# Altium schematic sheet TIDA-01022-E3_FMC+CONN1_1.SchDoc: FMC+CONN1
size 431 x 279 mm; Date: Not shown in title block; ApprovedBy: Not shown in title block; CheckedBy: Not shown in title block; Author: Not shown in title block; CompanyName: Not shown in title block; DrawnBy: Avinash N; Engineer: Not shown in title block; Organization: Not shown in title block; Address1: Not shown in title block; Address2: Not shown in title block; Address3: Not shown in title block; Address4: Not shown in title block; DocumentNumber: 1; Revision: Use project parameter SCH_Rev; SheetNumber: 17; SheetTotal: 26; PageSetup: Record=PageOptions¦CenterHorizontal=True¦CenterVertical=True¦PrintScale=1.00¦XCorrection=1.00¦YCorrection=1.00¦PrintKind=0¦BorderSize=5000000¦LeftOffset=0¦BottomOffset=0¦Orientation=2¦PaperLength=1000¦PaperWidth=1000¦Scale=100¦PaperSource=15¦PrintQuality=600¦MediaType=1¦DitherType=10¦PaperKind=Letter¦PrintScaleMode=1
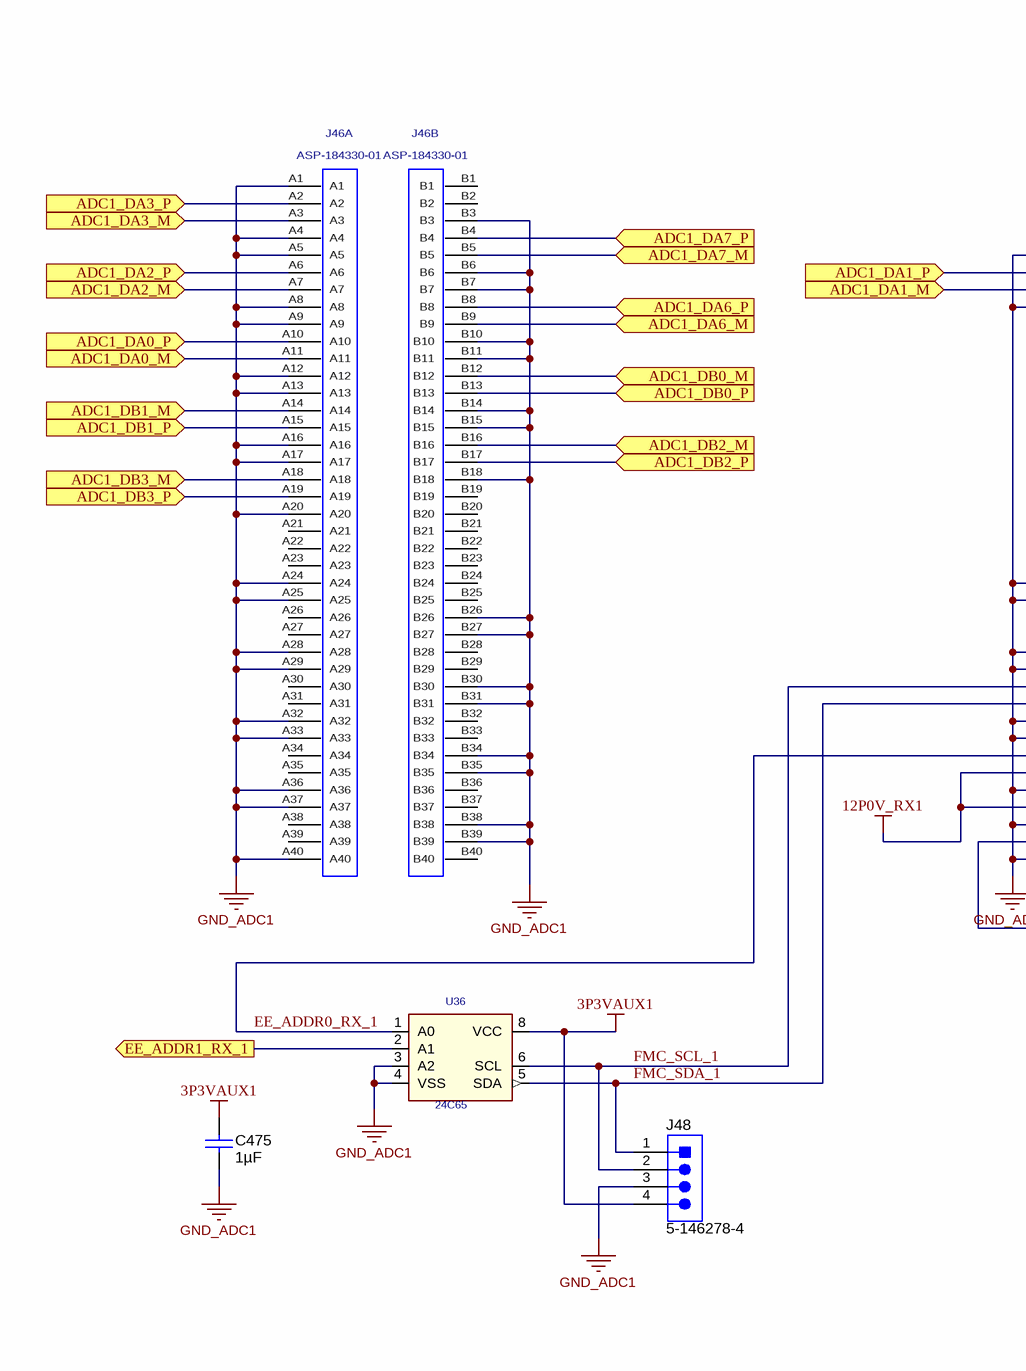
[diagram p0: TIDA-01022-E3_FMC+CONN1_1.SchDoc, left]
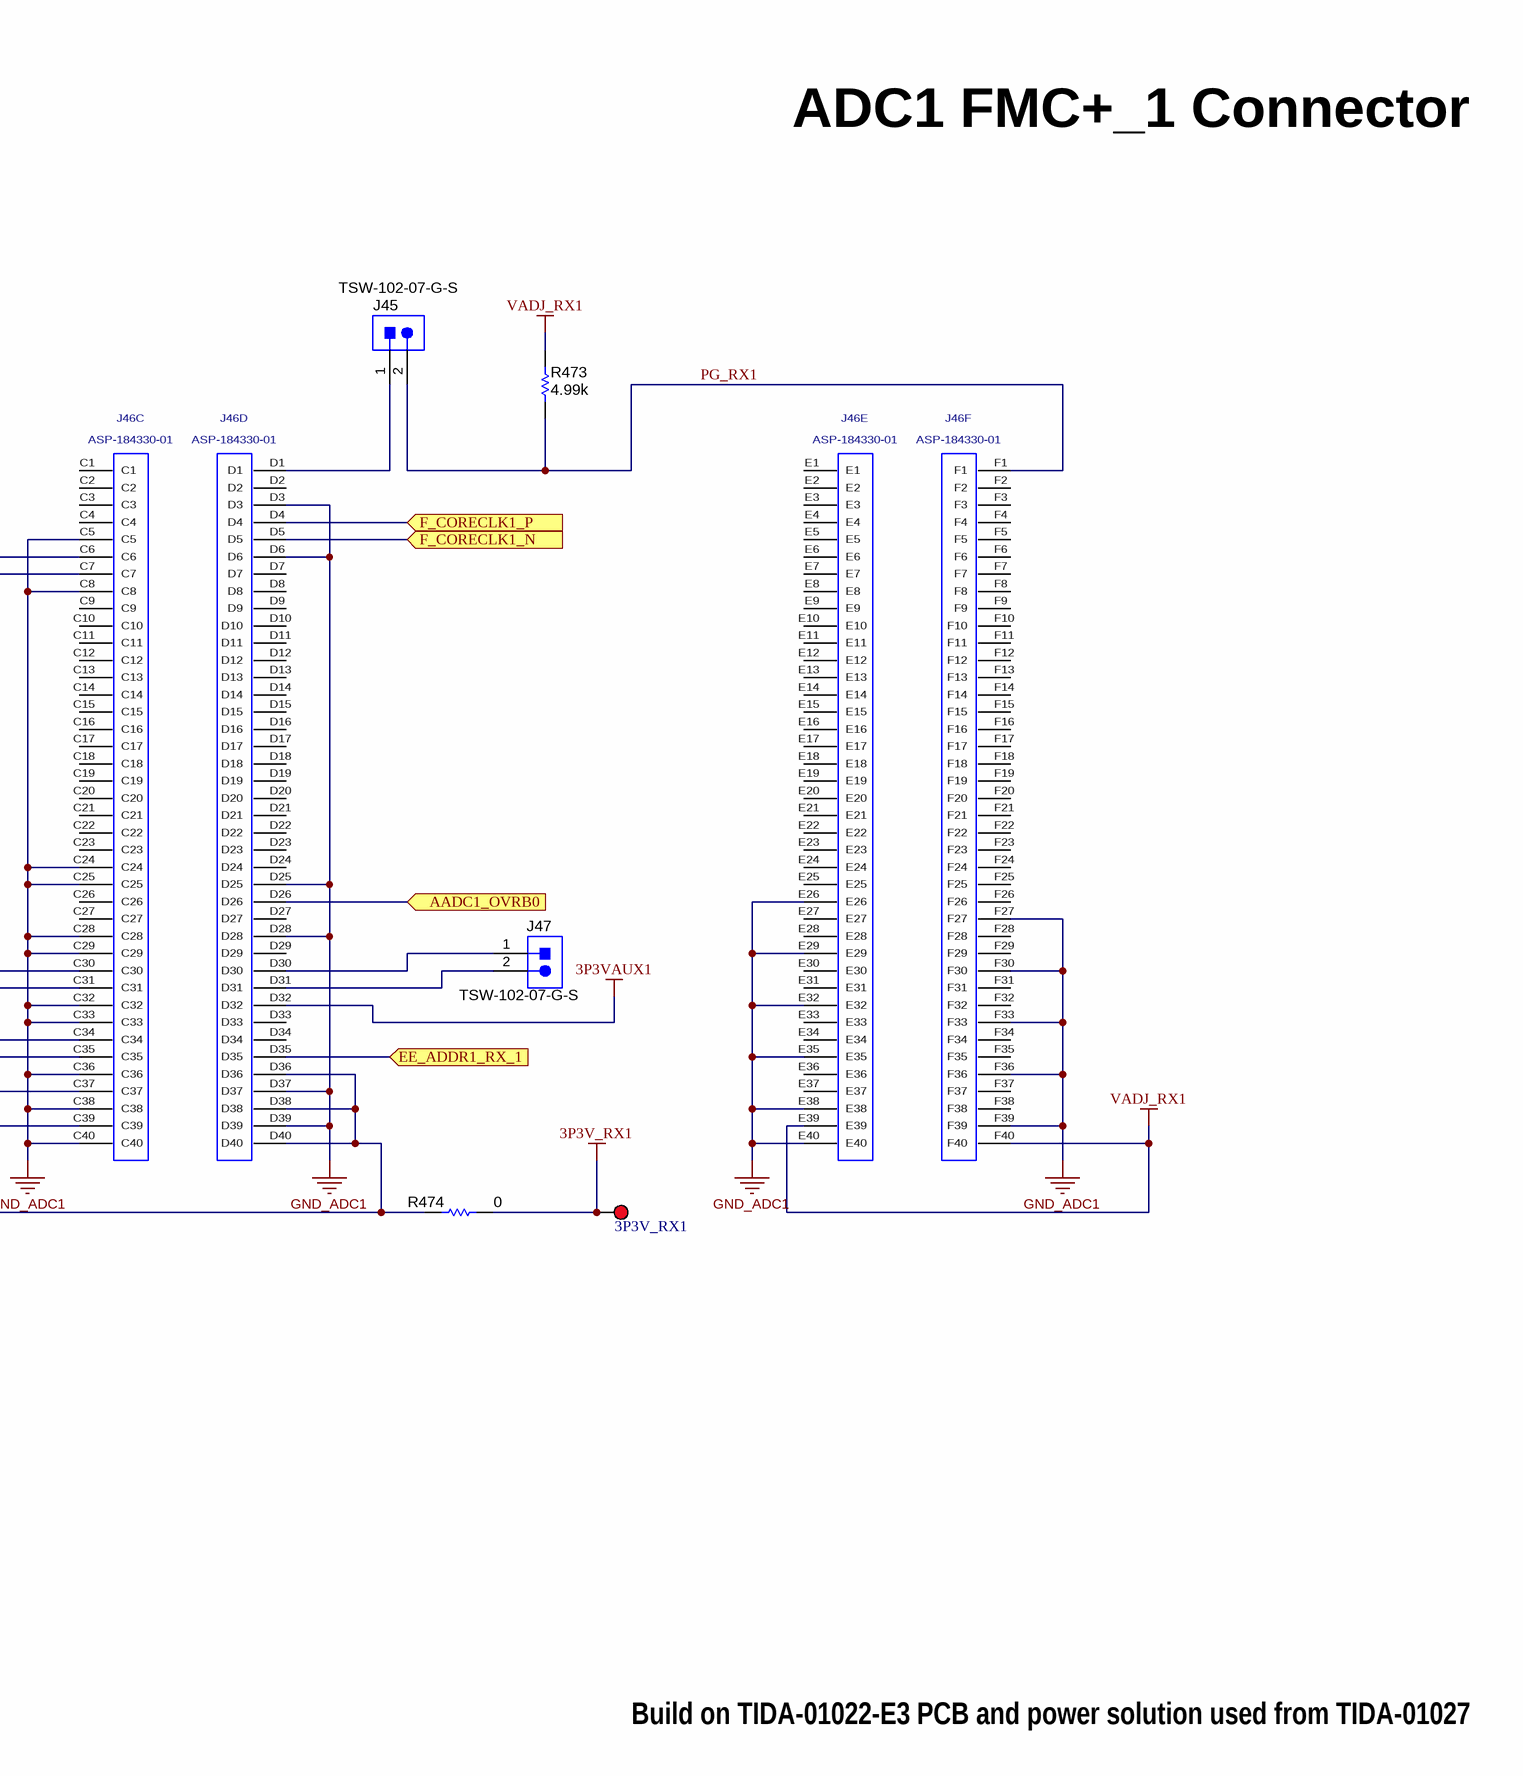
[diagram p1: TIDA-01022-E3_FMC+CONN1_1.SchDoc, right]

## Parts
3P3V_RX1  5000  [Keystone5000]  (value not drawn)
C475  ValueDisplayed: 1µF  [0603]  (hidden comment: C1608X5R1A105K080AC)
J45  TSW-102-07-G-S  [TSW-102-07-G-S]
J46  ASP-184330-01  [ASP-184330-01]  (parts A,B,C,D,E,F of 14)
J47  TSW-102-07-G-S  [TSW-102-07-G-S]
J48  5-146278-4  [TE_5-146278-4]
R473  ValueDisplayed: 4.99k  [0402]  (hidden comment: CRCW04024K99FKED)
R474  ValueDisplayed: 0  [0402]  (hidden comment: CRCW04020000Z0ED)
U36  24C65  [SOIC127P800X216-8N]

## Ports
AADC1_OVRB0 (in), ADC1_DA0_M (in), ADC1_DA0_P (in), ADC1_DA1_M (in), ADC1_DA1_P (in), ADC1_DA2_M (in), ADC1_DA2_P (in), ADC1_DA3_M (in), ADC1_DA3_P (in), ADC1_DA6_M (in), ADC1_DA6_P (in), ADC1_DA7_M (in), ADC1_DA7_P (in), ADC1_DB0_M (in), ADC1_DB0_P (in), ADC1_DB1_M (in), ADC1_DB1_P (in), ADC1_DB2_M (in), ADC1_DB2_P (in), ADC1_DB3_M (in), ADC1_DB3_P (in), EE_ADDR1_RX_1 (in), EE_ADDR1_RX_1 (out), F_CORECLK1_N (in), F_CORECLK1_P (in)

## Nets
3P3V_RX1: 3P3V_RX1.1 R474.1
3P3VAUX1: C475.1 J46.D32 J48.4 U36.8(VCC)
12P0V_RX1: J46.C35 J46.C37
GND_ADC1: C475.2 J46.A1 J46.A4 J46.A5 J46.A8 J46.A9 J46.A12 J46.A13 J46.A16 J46.A17 J46.A20 J46.A24 J46.A25 J46.A28 J46.A29 J46.A32 J46.A33 J46.A36 J46.A37 J46.A40 J46.B3 J46.B6 J46.B7 J46.B10 J46.B11 J46.B14 J46.B15 J46.B18 J46.B26 J46.B27 J46.B30 J46.B31 J46.B34 J46.B35 J46.B38 J46.B39 J46.C5 J46.C8 J46.C24 J46.C25 J46.C28 J46.C29 J46.C32 J46.C33 J46.C36 J46.C38 J46.C40 J46.D3 J46.D6 J46.D25 J46.D28 J46.D37 J46.D39 J46.E26 J46.E29 J46.E32 J46.E35 J46.E38 J46.E40 J46.F27 J46.F30 J46.F33 J46.F36 J46.F39 J48.3 U36.3(A2) U36.4(VSS)
VADJ_RX1: J46.E39 J46.F40 R473.2
AADC1_OVRB0: J46.D26 ; port AADC1_OVRB0
ADC1_DA0_M: J46.A11 ; port ADC1_DA0_M
ADC1_DA0_P: J46.A10 ; port ADC1_DA0_P
ADC1_DA1_M: J46.C7 ; port ADC1_DA1_M
ADC1_DA1_P: J46.C6 ; port ADC1_DA1_P
ADC1_DA2_M: J46.A7 ; port ADC1_DA2_M
ADC1_DA2_P: J46.A6 ; port ADC1_DA2_P
ADC1_DA3_M: J46.A3 ; port ADC1_DA3_M
ADC1_DA3_P: J46.A2 ; port ADC1_DA3_P
ADC1_DA6_M: J46.B9 ; port ADC1_DA6_M
ADC1_DA6_P: J46.B8 ; port ADC1_DA6_P
ADC1_DA7_M: J46.B5 ; port ADC1_DA7_M
ADC1_DA7_P: J46.B4 ; port ADC1_DA7_P
ADC1_DB0_M: J46.B12 ; port ADC1_DB0_M
ADC1_DB0_P: J46.B13 ; port ADC1_DB0_P
ADC1_DB1_M: J46.A14 ; port ADC1_DB1_M
ADC1_DB1_P: J46.A15 ; port ADC1_DB1_P
ADC1_DB2_M: J46.B16 ; port ADC1_DB2_M
ADC1_DB2_P: J46.B17 ; port ADC1_DB2_P
ADC1_DB3_M: J46.A18 ; port ADC1_DB3_M
ADC1_DB3_P: J46.A19 ; port ADC1_DB3_P
EE_ADDR0_RX_1: J46.C34 U36.1(A0)
EE_ADDR1_RX_1: J46.D35 U36.2(A1) ; port EE_ADDR1_RX_1
F_CORECLK1_N: J46.D5 ; port F_CORECLK1_N
F_CORECLK1_P: J46.D4 ; port F_CORECLK1_P
FMC_SCL_1: J46.C30 J48.2 U36.6(SCL)
FMC_SDA_1: J46.C31 J48.1 U36.5(SDA)
PG_RX1: J45.2 J46.F1 R473.1
NetJ45_1: J45.1 J46.D1
NetJ46_C39: J46.C39 J46.D36 J46.D38 J46.D40 R474.2
NetJ46_D30: J46.D30 J47.1
NetJ46_D31: J46.D31 J47.2

Not connected (* = marked no-connect by the designer): J46 A21 A22 A23 A26 A27 A30 A31 A34 A35 A38 A39 B1 B2 B19 B20 B21 B22 B23 B24 B25 B28 B29 B32 B33 B36 B37 B40 C1 C2 C3 C4 C9 C10 C11 C12 C13 C14 C15 C16 C17 C18 C19 C20 C21 C22 C23 C26 C27 D2 D7 D8 D9 D10 D11 D12 D13 D14 D15 D16 D17 D18 D19 D20 D21 D22 D23 D24 D27 D29 D33 D34 E1 E2 E3 E4 E5 E6 E7 E8 E9 E10 E11 E12 E13 E14 E15 E16 E17 E18 E19 E20 E21 E22 E23 E24 E25 E27 E28 E30 E31 E33 E34 E36 E37 F2 F3 F4 F5 F6 F7 F8 F9 F10 F11 F12 F13 F14 F15 F16 F17 F18 F19 F20 F21 F22 F23 F24 F25 F26 F28 F29 F31 F32 F34 F35 F37 F38

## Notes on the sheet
- ADC1 FMC+_1 Connector
- Build on TIDA-01022-E3 PCB and power solution used from TIDA-01027

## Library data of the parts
3P3V_RX1 = 5000: Test Point, Miniature, Red, TH; Manufacturer: Keystone; CompType: Test Point Loop; ContactFinish: Silver; Green_Lifecycle: Active; Green_REACh: Passed
C475 = C1608X5R1A105K080AC: CAP, CERM, 1 µF, 10 V, +/- 10%, X5R, 0603; Manufacturer: TDK; Polarized: N; CompType: Capacitor; Value: 1uF; U/M: EA; Cap_F: 0.000001; Tolerance_%: 10; Value1: Unknown; Value2: 10V; TaMin_C: -55; TaMax_C: 85; SizeArea_mm2: 1.28; SizeAreaWB_mm2: 4.68; SizeX_mm: 1.6; SizeY_mm: 0.8; SizeZ_mm: 1; AEC Category: Q200
J45 J47 = TSW-102-07-G-S: Header, 100mil, 2x1, Gold, TH; Manufacturer: Samtec; SymbolCreator: a0412235; Pitch_mm: 2.54; Gender: Male; Shrouded: N; Row_Count: 1; Current_A: 6.3; Voltage_V: 550; Cert_CSA: Y
J46 = ASP-184330-01: 14 ROW .050 PITCH TERMINAL ARRAY ASM.; Manufacturer: SAMTEC
J48 = 5-146278-4: Header, 100mil, 4x1, Tin, TH; Manufacturer: TE Connectivity; SymbolCreator: a0412235
R473 = CRCW04024K99FKED: RES, 4.99 k, 1%, 0.063 W, 0402; Manufacturer: Vishay-Dale; CompType: Resistor; Value: 4.99k; Res_ohm: 4990; Value_Code: 4k99; Tolerance_%: 1; Power_W: 0.063; Value2: 0.063W; VDC_V: 50; TempCo: 100 ppm/C; SizeArea_mm2: 0.5; SizeZ_mm: 0.6; EIA_Code: E96; U/M: EA; AEC Category: Q200
R474 = CRCW04020000Z0ED: RES, 0, 5%, 0.063 W, 0402; Manufacturer: Vishay-Dale; CompType: Resistor; Value: 0; Value_Code: 0000; Tolerance_%: 5; Power_W: 0.063; Value2: 0.063W; VDC_V: 50; TempCo: 200 ppm/C; SizeArea_mm2: 0.5; SizeX_mm: 1; SizeZ_mm: 0.6; EIA_Code: E24; U/M: EA; AEC Category: Q200
U36 = 24LC65: 64K I2C Smart Serial EEPROM, SOIC-8; PartNumber: 24C65T-I/SM; Manufacturer: MICROCHIP TECHNOLOGY_DNI; NC: 7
